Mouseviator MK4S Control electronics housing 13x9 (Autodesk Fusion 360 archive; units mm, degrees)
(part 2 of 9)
sketch "Sketch1" plane through (0, 0, 5) normal (0, 0, 1) x axis (-1, 0, 0)
  line L1 (-98.9644, -53.9879) -> (-98.9644, -59.9879)
  line L2 (-92.9644, -53.9879) -> (-98.9644, -53.9879)
  line L3 (-92.9644, -59.9879) -> (-92.9644, -53.9879)
  line L4 (-98.9644, -59.9879) -> (-92.9644, -59.9879)
  line L5 (-12.9644, 60.0121) -> (-12.9644, 66.0121)
  line L6 (-18.9644, 60.0121) -> (-12.9644, 60.0121)
  line L7 (-18.9644, 66.0121) -> (-18.9644, 60.0121)
  line L8 (-12.9644, 66.0121) -> (-18.9644, 66.0121)
  line L9 (-45.9644, -51.9879) -> (-20.9644, -51.9879)
  line L10 (-40.9644, -54.9879) -> (-45.9644, -51.9879)
  line L11 (-70.9644, -54.9879) -> (-40.9644, -54.9879)
  line L12 (-65.9644, -51.9879) -> (-70.9644, -54.9879)
  line L13 (-90.9644, -51.9879) -> (-65.9644, -51.9879)
  line L14 (-90.9644, -6.9879) -> (-90.9644, -51.9879)
  line L15 (-93.9644, -11.9879) -> (-90.9644, -6.9879)
  line L16 (-93.9644, 18.0121) -> (-93.9644, -11.9879)
  line L17 (-90.9644, 13.0121) -> (-93.9644, 18.0121)
  line L18 (-90.9644, 58.0121) -> (-90.9644, 13.0121)
  line L19 (-65.9644, 58.0121) -> (-90.9644, 58.0121)
  line L20 (-70.9644, 61.0121) -> (-65.9644, 58.0121)
  line L21 (-40.9644, 61.0121) -> (-70.9644, 61.0121)
  line L22 (-45.9644, 58.0121) -> (-40.9644, 61.0121)
  line L23 (-20.9644, 58.0121) -> (-45.9644, 58.0121)
  line L24 (-20.9644, 13.0121) -> (-20.9644, 58.0121)
  line L25 (-17.9644, 18.0121) -> (-20.9644, 13.0121)
  line L26 (-17.9644, -11.9879) -> (-17.9644, 18.0121)
  line L27 (-20.9644, -6.9879) -> (-17.9644, -11.9879)
  line L28 (-20.9644, -51.9879) -> (-20.9644, -6.9879)
  line L29 (-12.9644, -53.9879) -> (-18.9644, -53.9879)
  line L30 (-12.9644, -59.9879) -> (-12.9644, -53.9879)
  line L31 (-18.9644, -59.9879) -> (-12.9644, -59.9879)
  line L32 (-18.9644, -53.9879) -> (-18.9644, -59.9879)
  line L33 (-98.9644, 60.0121) -> (-92.9644, 60.0121)
  line L34 (-98.9644, 66.0121) -> (-98.9644, 60.0121)
  line L35 (-92.9644, 66.0121) -> (-98.9644, 66.0121)
  line L36 (-92.9644, 60.0121) -> (-92.9644, 66.0121)
  line L37 (-10.9644, -6.9879) -> (-10.9644, -61.9879)
  line L38 (-13.9644, -11.9879) -> (-10.9644, -6.9879)
  line L39 (-13.9644, 18.0121) -> (-13.9644, -11.9879)
  line L40 (-10.9644, 13.0121) -> (-13.9644, 18.0121)
  line L41 (-10.9644, 68.0121) -> (-10.9644, 13.0121)
  line L42 (-45.9644, 68.0121) -> (-10.9644, 68.0121)
  line L43 (-40.9644, 65.0121) -> (-45.9644, 68.0121)
  line L44 (-70.9644, 65.0121) -> (-40.9644, 65.0121)
  line L45 (-65.9644, 68.0121) -> (-70.9644, 65.0121)
  line L46 (-100.9644, 68.0121) -> (-65.9644, 68.0121)
  line L47 (-100.9644, 13.0121) -> (-100.9644, 68.0121)
  line L48 (-97.9644, 18.0121) -> (-100.9644, 13.0121)
  line L49 (-97.9644, -11.9879) -> (-97.9644, 18.0121)
  line L50 (-100.9644, -6.9879) -> (-97.9644, -11.9879)
  line L51 (-100.9644, -61.9879) -> (-100.9644, -6.9879)
  line L52 (-65.9644, -61.9879) -> (-100.9644, -61.9879)
  line L53 (-70.9644, -58.9879) -> (-65.9644, -61.9879)
  line L54 (-40.9644, -58.9879) -> (-70.9644, -58.9879)
  line L55 (-45.9644, -61.9879) -> (-40.9644, -58.9879)
  line L56 (-10.9644, -61.9879) -> (-45.9644, -61.9879)
  line L57 (-100.9644, -61.9879) -> (-10.9644, -61.9879)
  line L58 (-99.9644, -60.9879) -> (-100.9644, -61.9879)
  line L59 (-91.9644, -60.9879) -> (-99.9644, -60.9879)
  line L60 (-91.9644, -59.9879) -> (-91.9644, -60.9879)
  line L61 (-19.9644, -59.9879) -> (-91.9644, -59.9879)
  line L62 (-19.9644, -60.9879) -> (-19.9644, -59.9879)
  line L63 (-11.9644, -60.9879) -> (-19.9644, -60.9879)
  line L64 (-10.9644, -61.9879) -> (-11.9644, -60.9879)
  line L65 (-99.9437, -61.0379) -> (-100.8937, -61.9879)
  line L66 (-91.9144, -61.0379) -> (-99.9437, -61.0379)
  line L67 (-91.9144, -60.0379) -> (-91.9144, -61.0379)
  line L68 (-20.0144, -60.0379) -> (-91.9144, -60.0379)
  line L69 (-20.0144, -61.0379) -> (-20.0144, -60.0379)
  line L70 (-11.9851, -61.0379) -> (-20.0144, -61.0379)
  line L71 (-11.0351, -61.9879) -> (-11.9851, -61.0379)
  circle C1 centre (-24.4644, 61.5121) radius 1.7
  circle C2 centre (-93.9644, 54.5121) radius 1.7
  circle C3 centre (-87.4644, -55.4879) radius 1.7
  circle C4 centre (-17.4644, -48.4879) radius 1.7
  circle C5 centre (-24.4644, -55.4879) radius 1.7
  circle C6 centre (-93.9644, -48.4879) radius 1.7
  circle C7 centre (-87.4644, 61.5121) radius 1.7
  circle C8 centre (-17.4644, 54.5121) radius 1.7
  point P46 (-10.9644, -61.9879)
  point P74 (-10.9644, -61.9879)
  point P61 (-100.9644, -61.9879)
  point P76 (-100.9644, -61.9879)
  point P68 (-99.9644, -60.9879)
  point P77 (-99.9644, -60.9879)
  point P69 (-91.9644, -60.9879)
  point P78 (-91.9644, -60.9879)
  point P70 (-91.9644, -59.9879)
  point P79 (-91.9644, -59.9879)
  point P71 (-19.9644, -59.9879)
  point P80 (-19.9644, -59.9879)
  point P72 (-19.9644, -60.9879)
  point P81 (-19.9644, -60.9879)
  point P73 (-11.9644, -60.9879)
  point P82 (-11.9644, -60.9879)
  point P89 (-11.0351, -61.9879)
  point P90 (-100.8937, -61.9879)
  point P75 (-100.9644, -61.9879)
  coincident P46 P74
  coincident P61 P76
  coincident P68 P77
  coincident P69 P78
  coincident P70 P79
  coincident P71 P80
  coincident P72 P81
  coincident P73 P82
  coincident L56 P89
  coincident L52 P90
  dimension "column_lock_spacing" = 2
  dimension "d228" distance L57 L70 = 0.95 (= "side_wall_thick1")
  dimension "d229" distance L57 L68 = 1.95 (= "side_wall_thick2")
  dimension "d230" distance L57 L66 = 0.95 (= "side_wall_thick1")
  dimension "d231" distance P74 P75 = 90 (= "plate_height")
  dimension "d232" distance L64 L71 = 0.05 (= "wall_clearance")
  dimension "d233" distance L58 L65 = 0.05 (= "wall_clearance")
  dimension "d234" angle L57 L58 = 45 (= "wall_rorner_angle")
  dimension "d235" distance P74 L69 = 9.05 (= "side_wall_col_length")
  dimension "d244" distance P75 L67 = 9.05 (= "side_wall_col_length")
extrude "Extrude1" new body sketch "Sketch1" profile of L52 L53 L55 L56 blind 69.9 (= "column_height - ( 2 * wall_clearance )") from offset 0.05 (= "wall_clearance")
sketch "Sketch2" plane through (0, 61.9879, 0) normal (0, 1, 0) x axis (-1, 0, 0)
  line L1 (-11.0351, 74.95) -> (-100.8937, 74.95)
  line L2 (-100.8937, 74.95) -> (-100.8937, 5.05)
  line L3 (-11.0351, 74.95) -> (-11.0351, 5.05)
  line L4 (-11.0351, 5.05) -> (-100.8937, 5.05)
  line L5 (-11.0351, 74.95) -> (-11.0351, 5.05)
  line L6 (-100.8937, 74.95) -> (-11.0351, 74.95)
  line L7 (-100.8937, 5.05) -> (-100.8937, 74.95)
  line L8 (-90.8937, 64.95) -> (-21.0351, 64.95)
  line L9 (-90.8937, 15.05) -> (-90.8937, 64.95)
  line L10 (-21.0351, 15.05) -> (-90.8937, 15.05)
  line L11 (-21.0351, 64.95) -> (-21.0351, 15.05)
  circle C1 centre (-95.9644, 60) radius 1.7
  circle C2 centre (-95.9644, 20) radius 1.7
  circle C3 centre (-15.9644, 20) radius 1.7
  circle C4 centre (-15.9644, 60) radius 1.7
hole "Hole1" HoleDepth 4 HoleDiameter 3.4 TipAngle 118
mirror_component "MirrorComponent3"
derived_instance "DerivedInstance3"
extrude "Extrude7" add sketch "left side holes" profile of C1 L13 L14 L15 L16 along normal blind 1.45 (= "( top_cover_thickness / 2 ) - wall_clearance")
extrude "Extrude3" cut sketch "base" profile of L9 L10 L11 L12 L13 L14 L15 L16 L17 L18 L19 L20 L21 L22 L23 L24 along normal blind 1.5 (= "top_cover_thickness / 2")
extrude "Extrude2" add sketch "Sketch1" along normal blind 2.5 (= "plate_thick / 2")
extrude "Extrude4" cut sketch "Sketch1" profile of L13 L12 L15 L14 L16 L17 C2 C3 C4 C5 along normal blind 2.55 (= "( plate_thick / 2 ) + wall_clearance")
sketch "Sketch1" plane through (0, 0, 0) normal (0, 0, 1) x axis (1, 0, 0)
  line L1 (-15, -9) -> (-15, 21)
  line L2 (-7, 6) -> (-28, 6)
  line L3 (-18, 16) -> (-18, 6)
  line L4 (-18, -4) -> (-18, 6)
  line L5 (-15, 21) -> (-18, 16)
  line L6 (-15, -9) -> (-18, -4)
  line L7 (-21, -9) -> (-18, -4)
  line L8 (-18, -4) -> (-18, 6)
  line L9 (-18, 16) -> (-18, 6)
  line L10 (-21, 21) -> (-18, 16)
  line L11 (-21, -9) -> (-21, 21)
  line L12 (-15.05, 20.8195) -> (-18, 15.9028)
  line L13 (-15.05, -8.8195) -> (-15.05, 20.8195)
  line L14 (-15.05, -8.8195) -> (-18, -3.9028)
  line L15 (-20.95, -8.8195) -> (-18, -3.9028)
  line L16 (-20.95, -8.8195) -> (-20.95, 20.8195)
  line L17 (-20.95, 20.8195) -> (-18, 15.9028)
  line L18 (-16.5, -15) -> (-16.5, 22.7414)
  circle C1 centre (-16.5, 11) radius 0.75
  circle C2 centre (-16.5, 11) radius 0.675
  circle C3 centre (-16.5, 1) radius 0.675
  circle C4 centre (-19.5, 11) radius 0.675
  circle C5 centre (-19.5, 1) radius 0.675
  point P2 (-15, 21)
  point P13 (-21, 21)
  point P3 (-15, -9)
  point P10 (-21, -9)
  point P6 (-18, 6)
  point P11 (-18, 6)
  point P7 (-18, 16)
  point P12 (-18, 16)
  point P8 (-18, -4)
  point P9 (-18, -4)
  point P22 (-16.5, 11)
  vertical L1
  horizontal L2
  perpendicular L2 L3
  perpendicular L2 L4
  symmetric P2 L3 P13
  symmetric P3 L3 P10
  symmetric P6 L3 P11
  symmetric P7 L3 P12
  symmetric L3 P8 P9
  parallel L1 L18
  coincident L18 P22
  symmetric L2 C2 C3
  symmetric L4 C2 C4
  symmetric L4 C3 C5
  dimension "d49_1" distance P6 P7 = 10 (= "join_width1")
  dimension "d50_1" distance P6 P8 = 10 (= "join_width1")
  dimension "d51_1" distance P2 P3 = 30 (= "join_width2 * 2")
  dimension "d52_1" distance L1 L3 = 3 (= "join_depth")
  dimension "joiner_spacing_3" = -0.05
  dimension "d256_1" distance L9 L18 = 1.5 (= "join_depth / 2")
  dimension "d257_1" diameter C1 = 1.5 (= "join_key_d")
  dimension "d258_1" distance L2 P22 = 5 (= "join_key_distance")
extrude "Extrude1" new body sketch "Sketch1" profile of L13 L12 L15 L14 L16 L17 along normal blind 5 (= "plate_thick") named "d54_1"
extrude "Extrude4" cut sketch "Sketch1" profile of L13 L12 L15 L14 L16 L17 C2 C3 C4 C5 along normal blind 2.55 (= "( plate_thick / 2 ) + wall_clearance") named "d260_1"
sketch "Sketch1" plane through (0, 0, 0) normal (0, 0, 1) x axis (1, 0, 0)
  line L1 (-15, -9) -> (-15, 21)
  line L2 (-7, 6) -> (-28, 6)
  line L3 (-18, 16) -> (-18, 6)
  line L4 (-18, -4) -> (-18, 6)
  line L5 (-15, 21) -> (-18, 16)
  line L6 (-15, -9) -> (-18, -4)
  line L7 (-18, -4) -> (-18, 6)
  line L8 (-18, 16) -> (-18, 6)
  line L9 (-15.05, 20.8195) -> (-18, 15.9028)
  line L10 (-15.05, -8.8195) -> (-15.05, 20.8195)
  line L11 (-15.05, -8.8195) -> (-18, -3.9028)
  line L12 (-16.5, -15) -> (-16.5, 22.7414)
  circle C1 centre (-16.5, 11) radius 0.75
  circle C2 centre (-16.5, 11) radius 0.675
  circle C3 centre (-16.5, 1) radius 0.675
  point P6 (-18, 6)
  point P10 (-18, 6)
  point P7 (-18, 16)
  point P11 (-18, 16)
  point P8 (-18, -4)
  point P9 (-18, -4)
  point P17 (-16.5, 11)
  point P2 (-15, 21)
  point P3 (-15, -9)
  vertical L1
  horizontal L2
  perpendicular L2 L3
  perpendicular L2 L4
  symmetric P6 L3 P10
  symmetric P7 L3 P11
  symmetric L3 P8 P9
  parallel L1 L12
  coincident L12 P17
  symmetric L2 C2 C3
  dimension "d49_1_2" distance P6 P7 = 10 (= "join_width1")
  dimension "d50_1_2" distance P6 P8 = 10 (= "join_width1")
  dimension "d51_1_2" distance P2 P3 = 30 (= "join_width2 * 2")
  dimension "d52_1_2" distance L1 L3 = 3 (= "join_depth")
  dimension "joiner_spacing_3_2" = -0.05
  dimension "d256_1_2" distance L8 L12 = 1.5 (= "join_depth / 2")
  dimension "d257_1_2" diameter C1 = 1.5 (= "join_key_d")
  dimension "d258_1_2" distance L2 P17 = 5 (= "join_key_distance")
position "Position3"
extrude "Extrude5" new body sketch "Sketch1" profile of L3 L7 L10 L9 L11 C2 C3 along normal blind 5 (= "plate_thick")
extrude "Extrude6" cut sketch "Sketch1" profile of L3 L7 L10 L9 L11 C2 C3 along normal blind 2.55 (= "( plate_thick / 2 ) + wall_clearance")
extrude "Extrude4" cut sketch "base" profile of L1 L2 L3 L4 L25 L26 L27 L28 C1 C2 L29 L30 L31 L32 C3 C4 L33 L34 C5 L35 C6 L36 L37 L38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 blind -1.5 (= "-( top_cover_thickness / 2 )") from offset 3 (= "top_cover_thickness")
extrude "Extrude5" cut sketch "base" profile of C1 C2 C3 C4 C5 C6 C7 C8 no distance stored
sketch "Sketch1" plane through (0, 0, 0) normal (0, 0, 1) x axis (1, 0, 0)
  line L1 (-15, -9) -> (-15, 21)
  line L2 (-7, 6) -> (-28, 6)
  line L3 (-18, 16) -> (-18, 6)
  line L4 (-18, -4) -> (-18, 6)
  line L5 (-15, 21) -> (-18, 16)
  line L6 (-15, -9) -> (-18, -4)
  line L7 (-18, -4) -> (-18, 6)
  line L8 (-18, 16) -> (-18, 6)
  line L9 (-15.05, 20.8195) -> (-18, 15.9028)
  line L10 (-15.05, -8.8195) -> (-15.05, 20.8195)
  line L11 (-15.05, -8.8195) -> (-18, -3.9028)
  line L12 (-16.5, -15) -> (-16.5, 22.7414)
  circle C1 centre (-16.5, 11) radius 0.75
  circle C2 centre (-16.5, 11) radius 0.675
  circle C3 centre (-16.5, 1) radius 0.675
  point P6 (-18, 6)
  point P10 (-18, 6)
  point P7 (-18, 16)
  point P11 (-18, 16)
  point P8 (-18, -4)
  point P9 (-18, -4)
  point P17 (-16.5, 11)
  point P2 (-15, 21)
  point P3 (-15, -9)
  vertical L1
  horizontal L2
  perpendicular L2 L3
  perpendicular L2 L4
  symmetric P6 L3 P10
  symmetric P7 L3 P11
  symmetric L3 P8 P9
  parallel L1 L12
  coincident L12 P17
  symmetric L2 C2 C3
  dimension "d49_1_2_1" distance P6 P7 = 10 (= "join_width1")
  dimension "d50_1_2_1" distance P6 P8 = 10 (= "join_width1")
  dimension "d51_1_2_1" distance P2 P3 = 30 (= "join_width2 * 2")
  dimension "d52_1_2_1" distance L1 L3 = 3 (= "join_depth")
  dimension "joiner_spacing_3_2_1" = -0.05
  dimension "d256_1_2_1" distance L8 L12 = 1.5 (= "join_depth / 2")
  dimension "d257_1_2_1" diameter C1 = 1.5 (= "join_key_d")
  dimension "d258_1_2_1" distance L2 P17 = 5 (= "join_key_distance")
position "Position4"
extrude "Extrude5" new body sketch "Sketch1" profile of L3 L7 L10 L9 L11 C2 C3 along normal blind 3 (= "top_cover_thickness") named "d262_1"
extrude "Extrude6" cut sketch "Sketch1" profile of L3 L7 L10 L9 L11 C2 C3 along normal blind 1.55 (= "( top_cover_thickness / 2 ) + wall_clearance") named "d264_1"
sketch "Sketch1" plane through (0, 0, 0) normal (0, 0, 1) x axis (1, 0, 0)
  line L1 (-15, -9) -> (-15, 21)
  line L2 (-7, 6) -> (-28, 6)
  line L3 (-18, 16) -> (-18, 6)
  line L4 (-18, -4) -> (-18, 6)
  line L5 (-15, 21) -> (-18, 16)
  line L6 (-15, -9) -> (-18, -4)
  line L7 (-21, -9) -> (-18, -4)
  line L8 (-18, -4) -> (-18, 6)
  line L9 (-18, 16) -> (-18, 6)
  line L10 (-21, 21) -> (-18, 16)
  line L11 (-21, -9) -> (-21, 21)
  line L12 (-15.05, 20.8195) -> (-18, 15.9028)
  line L13 (-15.05, -8.8195) -> (-15.05, 20.8195)
  line L14 (-15.05, -8.8195) -> (-18, -3.9028)
  line L15 (-20.95, -8.8195) -> (-18, -3.9028)
  line L16 (-20.95, -8.8195) -> (-20.95, 20.8195)
  line L17 (-20.95, 20.8195) -> (-18, 15.9028)
  line L18 (-16.5, -15) -> (-16.5, 22.7414)
  circle C1 centre (-16.5, 11) radius 0.75
  circle C2 centre (-16.5, 11) radius 0.675
  circle C3 centre (-16.5, 1) radius 0.675
  circle C4 centre (-19.5, 11) radius 0.675
  circle C5 centre (-19.5, 1) radius 0.675
  point P2 (-15, 21)
  point P13 (-21, 21)
  point P3 (-15, -9)
  point P10 (-21, -9)
  point P6 (-18, 6)
  point P11 (-18, 6)
  point P7 (-18, 16)
  point P12 (-18, 16)
  point P8 (-18, -4)
  point P9 (-18, -4)
  point P22 (-16.5, 11)
  vertical L1
  horizontal L2
  perpendicular L2 L3
  perpendicular L2 L4
  symmetric P2 L3 P13
  symmetric P3 L3 P10
  symmetric P6 L3 P11
  symmetric P7 L3 P12
  symmetric L3 P8 P9
  parallel L1 L18
  coincident L18 P22
  symmetric L2 C2 C3
  symmetric L4 C2 C4
  symmetric L4 C3 C5
  dimension "d49_1_1" distance P6 P7 = 10 (= "join_width1")
  dimension "d50_1_1" distance P6 P8 = 10 (= "join_width1")
  dimension "d51_1_1" distance P2 P3 = 30 (= "join_width2 * 2")
  dimension "d52_1_1" distance L1 L3 = 3 (= "join_depth")
  dimension "joiner_spacing_3_3" = -0.05
  dimension "d256_1_1" distance L9 L18 = 1.5 (= "join_depth / 2")
  dimension "d257_1_1" diameter C1 = 1.5 (= "join_key_d")
  dimension "d258_1_1" distance L2 P22 = 5 (= "join_key_distance")
extrude "Extrude1" new body sketch "Sketch1" profile of L13 L12 L15 L14 L16 L17 C2 C3 C4 C5 along normal blind 3 (= "top_cover_thickness") named "d54_1_1"
extrude "Extrude4" cut sketch "Sketch1" profile of L13 L12 L15 L14 L16 L17 C2 C3 C4 C5 along normal blind 1.55 (= "( top_cover_thickness / 2 ) + wall_clearance") named "d260_1_1"
position "Position5"
sketch "base" plane through (0, 0, 0) normal (0, 0, 1) x axis (1, 0, 0)
  line L1 (12.9644, 53.9879) -> (18.9644, 53.9879)
  line L2 (12.9644, 59.9879) -> (12.9644, 53.9879)
  line L3 (18.9644, 59.9879) -> (12.9644, 59.9879)
  line L4 (18.9644, 53.9879) -> (18.9644, 59.9879)
  line L5 (13.0144, 54.0379) -> (18.9144, 54.0379)
  line L6 (13.0144, 59.9379) -> (13.0144, 54.0379)
  line L7 (18.9144, 59.9379) -> (13.0144, 59.9379)
  line L8 (18.9144, 54.0379) -> (18.9144, 59.9379)
  line L9 (11.9644, 52.9879) -> (19.9644, 52.9879)
  line L10 (11.9644, 60.9879) -> (11.9644, 52.9879)
  line L11 (19.9644, 60.9879) -> (11.9644, 60.9879)
  line L12 (19.9644, 52.9879) -> (19.9644, 60.9879)
  dimension "d67_1" = 0.05
  dimension "d68_1" = -1
extrude "Extrude2" new body sketch "base" profile of L1 L2 L3 L4 L9 L10 L11 L12 blind 70 (= "column_height") named "d73_1" from offset 5 (= "plate_thick") named "d72_1"
extrude "Extrude3" add sketch "Sketch1" profile of L36 L35 L38 L37 along normal blind 75 (= "plate_thick + column_height") named "d75_1"
sketch "supports bottom" plane through (0, 0, 5) normal (0, 0, 1) x axis (-1, 0, 0)
  line L1 (-98.9644, -53.9879) -> (-98.9644, -59.9879)
  line L2 (-92.9644, -53.9879) -> (-98.9644, -53.9879)
  line L3 (-92.9644, -59.9879) -> (-92.9644, -53.9879)
  line L4 (-98.9644, -59.9879) -> (-92.9644, -59.9879)
  line L5 (-12.9644, 60.0121) -> (-12.9644, 66.0121)
  line L6 (-18.9644, 60.0121) -> (-12.9644, 60.0121)
  line L7 (-18.9644, 66.0121) -> (-18.9644, 60.0121)
  line L8 (-12.9644, 66.0121) -> (-18.9644, 66.0121)
  line L9 (-45.9644, -51.9879) -> (-20.9644, -51.9879)
  line L10 (-40.9644, -54.9879) -> (-45.9644, -51.9879)
  line L11 (-70.9644, -54.9879) -> (-40.9644, -54.9879)
  line L12 (-65.9644, -51.9879) -> (-70.9644, -54.9879)
  line L13 (-90.9644, -51.9879) -> (-65.9644, -51.9879)
  line L14 (-90.9644, -6.9879) -> (-90.9644, -51.9879)
  line L15 (-93.9644, -11.9879) -> (-90.9644, -6.9879)
  line L16 (-93.9644, 18.0121) -> (-93.9644, -11.9879)
  line L17 (-90.9644, 13.0121) -> (-93.9644, 18.0121)
  line L18 (-90.9644, 58.0121) -> (-90.9644, 13.0121)
  line L19 (-65.9644, 58.0121) -> (-90.9644, 58.0121)
  line L20 (-70.9644, 61.0121) -> (-65.9644, 58.0121)
  line L21 (-40.9644, 61.0121) -> (-70.9644, 61.0121)
  line L22 (-45.9644, 58.0121) -> (-40.9644, 61.0121)
  line L23 (-20.9644, 58.0121) -> (-45.9644, 58.0121)
  line L24 (-20.9644, 13.0121) -> (-20.9644, 58.0121)
  line L25 (-17.9644, 18.0121) -> (-20.9644, 13.0121)
  line L26 (-17.9644, -11.9879) -> (-17.9644, 18.0121)
  line L27 (-20.9644, -6.9879) -> (-17.9644, -11.9879)
  line L28 (-20.9644, -51.9879) -> (-20.9644, -6.9879)
  line L29 (-12.9644, -53.9879) -> (-18.9644, -53.9879)
  line L30 (-12.9644, -59.9879) -> (-12.9644, -53.9879)
  line L31 (-18.9644, -59.9879) -> (-12.9644, -59.9879)
  line L32 (-18.9644, -53.9879) -> (-18.9644, -59.9879)
  line L33 (-98.9644, 60.0121) -> (-92.9644, 60.0121)
  line L34 (-98.9644, 66.0121) -> (-98.9644, 60.0121)
  line L35 (-92.9644, 66.0121) -> (-98.9644, 66.0121)
  line L36 (-92.9644, 60.0121) -> (-92.9644, 66.0121)
  line L37 (-10.9644, -6.9879) -> (-10.9644, -61.9879)
  line L38 (-13.9644, -11.9879) -> (-10.9644, -6.9879)
  line L39 (-13.9644, 18.0121) -> (-13.9644, -11.9879)
  line L40 (-10.9644, 13.0121) -> (-13.9644, 18.0121)
  line L41 (-10.9644, 68.0121) -> (-10.9644, 13.0121)
  line L42 (-45.9644, 68.0121) -> (-10.9644, 68.0121)
  line L43 (-40.9644, 65.0121) -> (-45.9644, 68.0121)
  line L44 (-70.9644, 65.0121) -> (-40.9644, 65.0121)
  line L45 (-65.9644, 68.0121) -> (-70.9644, 65.0121)
  line L46 (-100.9644, 68.0121) -> (-65.9644, 68.0121)
  line L47 (-100.9644, 13.0121) -> (-100.9644, 68.0121)
  line L48 (-97.9644, 18.0121) -> (-100.9644, 13.0121)
  line L49 (-97.9644, -11.9879) -> (-97.9644, 18.0121)
  line L50 (-100.9644, -6.9879) -> (-97.9644, -11.9879)
  line L51 (-100.9644, -61.9879) -> (-100.9644, -6.9879)
  line L52 (-65.9644, -61.9879) -> (-100.9644, -61.9879)
  line L53 (-70.9644, -58.9879) -> (-65.9644, -61.9879)
  line L54 (-40.9644, -58.9879) -> (-70.9644, -58.9879)
  line L55 (-45.9644, -61.9879) -> (-40.9644, -58.9879)
  line L56 (-10.9644, -61.9879) -> (-45.9644, -61.9879)
  line L57 (-11.9644, -52.9879) -> (-19.9644, -52.9879)
  line L58 (-11.9644, -60.9879) -> (-11.9644, -52.9879)
  line L59 (-19.9644, -60.9879) -> (-11.9644, -60.9879)
  line L60 (-19.9644, -52.9879) -> (-19.9644, -60.9879)
  line L61 (-14.9644, -52.9879) -> (-12.9644, -52.9879)
  line L62 (-14.9644, -42.9879) -> (-14.9644, -52.9879)
  line L63 (-12.9644, -42.9879) -> (-14.9644, -42.9879)
  line L64 (-12.9644, -52.9879) -> (-12.9644, -42.9879)
  line L65 (-29.9644, -59.9879) -> (-19.9644, -59.9879)
  line L66 (-29.9644, -57.9879) -> (-29.9644, -59.9879)
  line L67 (-19.9644, -57.9879) -> (-29.9644, -57.9879)
  line L68 (-19.9644, -59.9879) -> (-19.9644, -57.9879)
  circle C1 centre (-24.4644, 61.5121) radius 1.7
  circle C2 centre (-93.9644, 54.5121) radius 1.7
  circle C3 centre (-87.4644, -55.4879) radius 1.7
  circle C4 centre (-17.4644, -48.4879) radius 1.7
  circle C5 centre (-24.4644, -55.4879) radius 1.7
  circle C6 centre (-93.9644, -48.4879) radius 1.7
  circle C7 centre (-87.4644, 61.5121) radius 1.7
  circle C8 centre (-17.4644, 54.5121) radius 1.7
  circle C9 centre (-17.4644, -48.4879) radius 1.7
  circle C10 centre (-24.4644, -55.4879) radius 1.7
  circle C11 centre (-17.4644, -48.4879) radius 3.15
  circle C12 centre (-24.4644, -55.4879) radius 3.15
  point P70 (-12.9644, -52.9879)
  point P74 (-19.9644, -59.9879)
  point P71 (-14.9644, -52.9879)
  point P73 (-12.9644, -42.9879)
  point P75 (-29.9644, -59.9879)
  point P77 (-19.9644, -57.9879)
  horizontal L61
  vertical L62
  horizontal L63
  vertical L64
  coincident L57 P70
  horizontal L65
  vertical L66
  horizontal L67
  vertical L68
  coincident L60 P74
  concentric C9 C11
  concentric C10 C12
  dimension "column_support_width_1" distance P70 P71 = 2
  dimension "column_support_height_1" distance P70 P73 = 10
  dimension "d79_1" distance P74 P75 = 10 (= "column_support_height_1")
  dimension "d80_1" distance P74 P77 = 2 (= "column_support_width_1")
  dimension "M3_head_d_1" diameter C11 = 6.3
  dimension "d85_1" diameter C12 = 6.3 (= "M3_head_d_1")
extrude "Extrude5" add sketch "supports bottom" profile of L53 L57 L60 L61 L62 L63 L64 L65 L66 L67 L68 C11 C12 along normal blind 10 (= "column_support_height_1") named "d86_1"
chamfer "Chamfer2" distance 10 (= "column_support_height_1") named "d88_1"
sketch "left side holes" plane through (0, 0, 75) normal (0, 0, 1) x axis (-1, 0, 0)
  line L1 (-11.9644, -60.9879) -> (-19.9644, -60.9879)
  line L2 (-11.9644, -52.9879) -> (-11.9644, -60.9879)
  line L3 (-19.9644, -52.9879) -> (-11.9644, -52.9879)
  line L4 (-19.9644, -60.9879) -> (-19.9644, -52.9879)
  line L5 (-19.9644, -57.9879) -> (-29.9644, -57.9879)
  line L6 (-19.9644, -59.9879) -> (-19.9644, -57.9879)
  line L7 (-29.9644, -59.9879) -> (-19.9644, -59.9879)
  line L8 (-29.9644, -57.9879) -> (-29.9644, -59.9879)
  line L9 (-14.9644, -42.9879) -> (-14.9644, -52.9879)
  line L10 (-12.9644, -42.9879) -> (-14.9644, -42.9879)
  line L11 (-14.9644, -52.9879) -> (-12.9644, -52.9879)
  line L12 (-12.9644, -52.9879) -> (-12.9644, -42.9879)
  line L13 (-18.9144, -59.9379) -> (-13.0144, -59.9379)
  line L14 (-18.9144, -54.0379) -> (-18.9144, -59.9379)
  line L15 (-13.0144, -54.0379) -> (-18.9144, -54.0379)
  line L16 (-13.0144, -59.9379) -> (-13.0144, -54.0379)
  line L17 (-18.9644, -59.9879) -> (-12.9644, -59.9879)
  line L18 (-18.9644, -53.9879) -> (-18.9644, -59.9879)
  line L19 (-12.9644, -53.9879) -> (-18.9644, -53.9879)
  line L20 (-12.9644, -59.9879) -> (-12.9644, -53.9879)
  circle C1 centre (-15.9644, -56.9879) radius 1.7
  dimension "M3_d_1" diameter C1 = 3.4
extrude "Extrude6" add sketch "left side holes" profile of L3 L4 L5 L6 L7 L8 L9 L10 L11 L12 against normal blind 10 named "d90_1" (magnitude of "-column_support_height_1")
chamfer "Chamfer3" distance 10 (= "column_support_height_1") named "d92_1"
hole "Hole1" HoleDepth 10 (= "column_support_height_1") named "d93_1" HoleDiameter 3.4 named "d94_1" TipAngle 118 named "d95_1"
sketch "Sketch4" plane through (0, 60.9879, 0) normal (0, 1, 0) x axis (-1, 0, 0)
  line L1 (-11.9644, 5) -> (-19.9644, 5)
  line L2 (-11.9644, 75) -> (-11.9644, 5)
  line L3 (-19.9644, 75) -> (-11.9644, 75)
  line L4 (-19.9644, 5) -> (-19.9644, 75)
  line L5 (-23.511, 60) -> (-11.9644, 60)
  line L6 (-25, 20) -> (-11.9644, 20)
  circle C1 centre (-15.9644, 60) radius 1.7
  circle C2 centre (-15.9644, 20) radius 1.7
  point P7 (-11.9644, 60)
  point P8 (-11.9644, 60)
  point P6 (-11.9644, 20)
  point P10 (-11.9644, 20)
  point P12 (-15.9644, 60)
  point P13 (-15.9644, 20)
  coincident P7 P8
  perpendicular L4 L5
  coincident P6 P10
  perpendicular L2 L6
  coincident L5 P12
  coincident L6 P13
  dimension "d103_1" diameter C1 = 3.4 (= "M3_d_1")
  dimension "d104_1" diameter C2 = 3.4 (= "M3_d_1")
  dimension "d105_1" distance L2 P12 = 4 (= "support_column_side / 2")
  dimension "d106_1" distance L2 P13 = 4 (= "support_column_side / 2")
hole "Hole3" HoleDepth 5.76 (= "support_column_side * 0.72") named "d110_1" HoleDiameter 3.4 named "d111_1" TipAngle 180 named "d112_1"
extrude "Extrude7" add sketch "left side holes" profile of C1 L13 L14 L15 L16 along normal blind 1.45 (= "( top_cover_thickness / 2 ) - wall_clearance") named "d236_1"
position "Position6"
work_plane "WorkPlane3" AlongDistance 1 (= "plate_square_thick - side_wall_col_length + wall_clearance")
sketch "Sketch5" plane through (11.9644, 0, 0) normal (-1, 0, 0) x axis (0, -1, 0)
  line L1 (-52.9879, 5) -> (-60.9879, 5)
  line L2 (-52.9879, 75) -> (-52.9879, 5)
  line L3 (-60.9879, 75) -> (-52.9879, 75)
  line L4 (-60.9879, 5) -> (-60.9879, 75)
  line L5 (-56.5129, 75) -> (-60.9879, 75)
  line L6 (-56.5129, 65) -> (-56.5129, 75)
  line L7 (-60.9879, 65) -> (-56.5129, 65)
  line L8 (-60.9879, 75) -> (-60.9879, 65)
  line L9 (-56.4129, 5) -> (-60.9879, 5)
  line L10 (-56.4129, 15) -> (-56.4129, 5)
  line L11 (-60.9879, 15) -> (-56.4129, 15)
  line L12 (-60.9879, 5) -> (-60.9879, 15)
  point P5 (-60.9879, 75)
  point P6 (-60.9879, 75)
  point P2 (-60.9879, 5)
  point P10 (-60.9879, 5)
  point P7 (-56.5129, 75)
  point P11 (-56.4129, 5)
  point P13 (-60.9879, 15)
  horizontal L5
  vertical L6
  horizontal L7
  vertical L8
  coincident P5 P6
  horizontal L9
  vertical L10
  horizontal L11
  vertical L12
  coincident P2 P10
  dimension "d271" distance P6 P7 = 4.475 (= "side_wall_col_length / 2 - wall_clearance")
  dimension "d272" distance L5 L7 = 10 (= "column_support_height")
  dimension "d273" distance P10 P11 = 4.575 (= "side_wall_col_length / 2 + wall_clearance")
  dimension "d274" distance P10 P13 = 10 (= "column_support_height")
extrude "Extrude8" add sketch "Sketch5" profile of L1 L3 L4 L5 L6 L7 L8 L9 L10 L11 L12 along normal blind 2 (= "2 * ( plate_square_thick - side_wall_col_length + wall_clearance )")
mirror "Mirror1" mirrorStitchTolerance 0.1
sketch "Sketch1" plane through (0, 0, 5) normal (0, 0, 1) x axis (-1, 0, 0)
  line L1 (-98.9644, -53.9879) -> (-98.9644, -59.9879)
  line L2 (-92.9644, -53.9879) -> (-98.9644, -53.9879)
  line L3 (-92.9644, -59.9879) -> (-92.9644, -53.9879)
  line L4 (-98.9644, -59.9879) -> (-92.9644, -59.9879)
  line L5 (-98.9644, 60.0121) -> (-92.9644, 60.0121)
  line L6 (-98.9644, 66.0121) -> (-98.9644, 60.0121)
  line L7 (-92.9644, 66.0121) -> (-98.9644, 66.0121)
  line L8 (-92.9644, 60.0121) -> (-92.9644, 66.0121)
  line L9 (-12.9644, 60.0121) -> (-12.9644, 66.0121)
  line L10 (-18.9644, 60.0121) -> (-12.9644, 60.0121)
  line L11 (-18.9644, 66.0121) -> (-18.9644, 60.0121)
  line L12 (-12.9644, 66.0121) -> (-18.9644, 66.0121)
  line L13 (-12.9644, -53.9879) -> (-18.9644, -53.9879)
  line L14 (-12.9644, -59.9879) -> (-12.9644, -53.9879)
  line L15 (-18.9644, -59.9879) -> (-12.9644, -59.9879)
  line L16 (-18.9644, -53.9879) -> (-18.9644, -59.9879)
  line L17 (-45.9644, -51.9879) -> (-20.9644, -51.9879)
  line L18 (-40.9644, -54.9879) -> (-45.9644, -51.9879)
  line L19 (-70.9644, -54.9879) -> (-40.9644, -54.9879)
  line L20 (-65.9644, -51.9879) -> (-70.9644, -54.9879)
  line L21 (-90.9644, -51.9879) -> (-65.9644, -51.9879)
  line L22 (-90.9644, -6.9879) -> (-90.9644, -51.9879)
  line L23 (-93.9644, -11.9879) -> (-90.9644, -6.9879)
  line L24 (-93.9644, 18.0121) -> (-93.9644, -11.9879)
  line L25 (-90.9644, 13.0121) -> (-93.9644, 18.0121)
  line L26 (-90.9644, 58.0121) -> (-90.9644, 13.0121)
  line L27 (-65.9644, 58.0121) -> (-90.9644, 58.0121)
  line L28 (-70.9644, 61.0121) -> (-65.9644, 58.0121)
  line L29 (-40.9644, 61.0121) -> (-70.9644, 61.0121)
  line L30 (-45.9644, 58.0121) -> (-40.9644, 61.0121)
  line L31 (-20.9644, 58.0121) -> (-45.9644, 58.0121)
  line L32 (-20.9644, 13.0121) -> (-20.9644, 58.0121)
  line L33 (-17.9644, 18.0121) -> (-20.9644, 13.0121)
  line L34 (-17.9644, -11.9879) -> (-17.9644, 18.0121)
  line L35 (-20.9644, -6.9879) -> (-17.9644, -11.9879)
  line L36 (-20.9644, -51.9879) -> (-20.9644, -6.9879)
  line L37 (-10.9644, -6.9879) -> (-10.9644, -61.9879)
  line L38 (-13.9644, -11.9879) -> (-10.9644, -6.9879)
  line L39 (-13.9644, 18.0121) -> (-13.9644, -11.9879)
  line L40 (-10.9644, 13.0121) -> (-13.9644, 18.0121)
  line L41 (-10.9644, 68.0121) -> (-10.9644, 13.0121)
  line L42 (-45.9644, 68.0121) -> (-10.9644, 68.0121)
  line L43 (-40.9644, 65.0121) -> (-45.9644, 68.0121)
  line L44 (-70.9644, 65.0121) -> (-40.9644, 65.0121)
  line L45 (-65.9644, 68.0121) -> (-70.9644, 65.0121)
  line L46 (-100.9644, 68.0121) -> (-65.9644, 68.0121)
  line L47 (-100.9644, 13.0121) -> (-100.9644, 68.0121)
  line L48 (-97.9644, 18.0121) -> (-100.9644, 13.0121)
  line L49 (-97.9644, -11.9879) -> (-97.9644, 18.0121)
  line L50 (-100.9644, -6.9879) -> (-97.9644, -11.9879)
  line L51 (-100.9644, -61.9879) -> (-100.9644, -6.9879)
  line L52 (-65.9644, -61.9879) -> (-100.9644, -61.9879)
  line L53 (-70.9644, -58.9879) -> (-65.9644, -61.9879)
  line L54 (-40.9644, -58.9879) -> (-70.9644, -58.9879)
  line L55 (-45.9644, -61.9879) -> (-40.9644, -58.9879)
  line L56 (-10.9644, -61.9879) -> (-45.9644, -61.9879)
  line L57 (-45.9644, -51.9879) -> (-20.9644, -51.9879)
  line L58 (-40.9644, -54.9879) -> (-55.9644, -54.9879)
  line L59 (-40.9644, -54.9879) -> (-45.9644, -51.9879)
  line L60 (-65.9644, -51.9879) -> (-70.9644, -54.9879)
  line L61 (-70.9644, -54.9879) -> (-55.9644, -54.9879)
  line L62 (-65.9644, -51.9879) -> (-90.9644, -51.9879)
  line L63 (-90.9644, -6.9879) -> (-90.9644, -51.9879)
  line L64 (-93.9644, -11.9879) -> (-93.9644, 3.0121)
  line L65 (-93.9644, -11.9879) -> (-90.9644, -6.9879)
  line L66 (-93.9644, 18.0121) -> (-90.9644, 13.0121)
  line L67 (-93.9644, 18.0121) -> (-93.9644, 3.0121)
  line L68 (-90.9644, 58.0121) -> (-90.9644, 13.0121)
  line L69 (-65.9644, 58.0121) -> (-90.9644, 58.0121)
  line L70 (-40.9644, 61.0121) -> (-45.9644, 58.0121)
  line L71 (-40.9644, 61.0121) -> (-55.9644, 61.0121)
  line L72 (-70.9644, 61.0121) -> (-55.9644, 61.0121)
  line L73 (-65.9644, 58.0121) -> (-70.9644, 61.0121)
  line L74 (-45.9644, 58.0121) -> (-20.9644, 58.0121)
  line L75 (-20.9644, 13.0121) -> (-20.9644, 58.0121)
  line L76 (-17.9644, 18.0121) -> (-17.9644, 3.0121)
  line L77 (-17.9644, -11.9879) -> (-17.9644, 3.0121)
  line L78 (-17.9644, -11.9879) -> (-20.9644, -6.9879)
  line L79 (-17.9644, 18.0121) -> (-20.9644, 13.0121)
  line L80 (-20.9644, -6.9879) -> (-20.9644, -51.9879)
  line L81 (-65.7839, -51.9379) -> (-70.7839, -54.9379)
  line L82 (-90.9144, -51.9379) -> (-65.7839, -51.9379)
  line L83 (-90.9144, -6.8074) -> (-90.9144, -51.9379)
  line L84 (-93.9144, -11.8074) -> (-90.9144, -6.8074)
  line L85 (-93.9144, 17.8316) -> (-93.9144, -11.8074)
  line L86 (-90.9144, 12.8316) -> (-93.9144, 17.8316)
  line L87 (-90.9144, 57.9621) -> (-90.9144, 12.8316)
  line L88 (-65.7839, 57.9621) -> (-90.9144, 57.9621)
  line L89 (-70.7839, 60.9621) -> (-65.7839, 57.9621)
  line L90 (-41.1449, 60.9621) -> (-70.7839, 60.9621)
  line L91 (-46.1449, 57.9621) -> (-41.1449, 60.9621)
  line L92 (-21.0144, 57.9621) -> (-46.1449, 57.9621)
  line L93 (-21.0144, 12.8316) -> (-21.0144, 57.9621)
  line L94 (-18.0144, 17.8316) -> (-21.0144, 12.8316)
  line L95 (-18.0144, -11.8074) -> (-18.0144, 17.8316)
  line L96 (-21.0144, -6.8074) -> (-18.0144, -11.8074)
  line L97 (-21.0144, -51.9379) -> (-21.0144, -6.8074)
  line L98 (-46.1449, -51.9379) -> (-21.0144, -51.9379)
  line L99 (-41.1449, -54.9379) -> (-46.1449, -51.9379)
  line L100 (-70.7839, -54.9379) -> (-41.1449, -54.9379)
  line L101 (-90.9144, 12.8316) -> (-90.9144, -6.8074)
  line L102 (-46.1449, -51.9379) -> (-65.7839, -51.9379)
  line L103 (-21.0144, 12.8316) -> (-21.0144, -6.8074)
  line L104 (-65.7839, 57.9621) -> (-46.1449, 57.9621)
  line L105 (-80.9144, -41.9379) -> (-31.0144, -41.9379)
  line L106 (-80.9144, 47.9621) -> (-80.9144, -41.9379)
  line L107 (-31.0144, 47.9621) -> (-80.9144, 47.9621)
  line L108 (-31.0144, -41.9379) -> (-31.0144, 47.9621)
  circle C1 centre (-24.4644, 61.5121) radius 1.7
  circle C2 centre (-93.9644, 54.5121) radius 1.7
  circle C3 centre (-87.4644, -55.4879) radius 1.7
  circle C4 centre (-17.4644, -48.4879) radius 1.7
  circle C5 centre (-24.4644, -55.4879) radius 1.7
  circle C6 centre (-93.9644, -48.4879) radius 1.7
  circle C7 centre (-87.4644, 61.5121) radius 1.7
  circle C8 centre (-17.4644, 54.5121) radius 1.7
  circle C9 centre (-60.9644, -53.4879) radius 0.75
  circle C10 centre (-50.9644, -53.4879) radius 0.75
  circle C11 centre (-92.4644, -1.9879) radius 0.75
  circle C12 centre (-92.4644, 8.0121) radius 0.75
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  horizontal L105
  vertical L106
  horizontal L107
  vertical L108
  dimension "d279" = 0.05 (= "wall_clearance")
  dimension "d289" distance L82 L105 = 10 (= "plate_square_thick")
  dimension "d290" distance L83 L106 = 10 (= "plate_square_thick")
  dimension "d291" distance L97 L108 = 10 (= "plate_square_thick")
  dimension "d292" distance L88 L107 = 10 (= "plate_square_thick")
extrude "Extrude1" new body sketch "Sketch1" along normal blind 5 (= "plate_thick")
extrude "Extrude2" add sketch "Sketch1" blind -2.45 (= "-( plate_thick / 2 ) + wall_clearance") from offset 5 (= "plate_thick")
sketch "base" plane through (0, 0, 0) normal (0, 0, 1) x axis (1, 0, 0)
  line L1 (12.9644, 53.9879) -> (18.9644, 53.9879)
  line L2 (12.9644, 59.9879) -> (12.9644, 53.9879)
  line L3 (18.9644, 59.9879) -> (12.9644, 59.9879)
  line L4 (18.9644, 53.9879) -> (18.9644, 59.9879)
  line L5 (13.0144, 54.0379) -> (18.9144, 54.0379)
  line L6 (13.0144, 59.9379) -> (13.0144, 54.0379)
  line L7 (18.9144, 59.9379) -> (13.0144, 59.9379)
  line L8 (18.9144, 54.0379) -> (18.9144, 59.9379)
  line L9 (11.9644, 52.9879) -> (19.9644, 52.9879)
  line L10 (11.9644, 60.9879) -> (11.9644, 52.9879)
  line L11 (19.9644, 60.9879) -> (11.9644, 60.9879)
  line L12 (19.9644, 52.9879) -> (19.9644, 60.9879)
  dimension "d67_1_1" = 0.05
  dimension "d68_1_1" = -1
extrude "Extrude2" new body sketch "base" profile of L1 L2 L3 L4 L9 L10 L11 L12 blind 70 (= "column_height") named "d73_1_1" from offset 5 (= "plate_thick") named "d72_1_1"
extrude "Extrude3" add sketch "Sketch1" profile of L36 L35 L38 L37 along normal blind 75 (= "plate_thick + column_height") named "d75_1_1"
sketch "supports bottom" plane through (0, 0, 5) normal (0, 0, 1) x axis (-1, 0, 0)
  line L1 (-98.9644, -53.9879) -> (-98.9644, -59.9879)
  line L2 (-92.9644, -53.9879) -> (-98.9644, -53.9879)
  line L3 (-92.9644, -59.9879) -> (-92.9644, -53.9879)
  line L4 (-98.9644, -59.9879) -> (-92.9644, -59.9879)
  line L5 (-12.9644, 60.0121) -> (-12.9644, 66.0121)
  line L6 (-18.9644, 60.0121) -> (-12.9644, 60.0121)
  line L7 (-18.9644, 66.0121) -> (-18.9644, 60.0121)
  line L8 (-12.9644, 66.0121) -> (-18.9644, 66.0121)
  line L9 (-45.9644, -51.9879) -> (-20.9644, -51.9879)
  line L10 (-40.9644, -54.9879) -> (-45.9644, -51.9879)
  line L11 (-70.9644, -54.9879) -> (-40.9644, -54.9879)
  line L12 (-65.9644, -51.9879) -> (-70.9644, -54.9879)
  line L13 (-90.9644, -51.9879) -> (-65.9644, -51.9879)
  line L14 (-90.9644, -6.9879) -> (-90.9644, -51.9879)
  line L15 (-93.9644, -11.9879) -> (-90.9644, -6.9879)
  line L16 (-93.9644, 18.0121) -> (-93.9644, -11.9879)
  line L17 (-90.9644, 13.0121) -> (-93.9644, 18.0121)
  line L18 (-90.9644, 58.0121) -> (-90.9644, 13.0121)
  line L19 (-65.9644, 58.0121) -> (-90.9644, 58.0121)
  line L20 (-70.9644, 61.0121) -> (-65.9644, 58.0121)
  line L21 (-40.9644, 61.0121) -> (-70.9644, 61.0121)
  line L22 (-45.9644, 58.0121) -> (-40.9644, 61.0121)
  line L23 (-20.9644, 58.0121) -> (-45.9644, 58.0121)
  line L24 (-20.9644, 13.0121) -> (-20.9644, 58.0121)
  line L25 (-17.9644, 18.0121) -> (-20.9644, 13.0121)
  line L26 (-17.9644, -11.9879) -> (-17.9644, 18.0121)
  line L27 (-20.9644, -6.9879) -> (-17.9644, -11.9879)
  line L28 (-20.9644, -51.9879) -> (-20.9644, -6.9879)
  line L29 (-12.9644, -53.9879) -> (-18.9644, -53.9879)
  line L30 (-12.9644, -59.9879) -> (-12.9644, -53.9879)
  line L31 (-18.9644, -59.9879) -> (-12.9644, -59.9879)
  line L32 (-18.9644, -53.9879) -> (-18.9644, -59.9879)
  line L33 (-98.9644, 60.0121) -> (-92.9644, 60.0121)
  line L34 (-98.9644, 66.0121) -> (-98.9644, 60.0121)
  line L35 (-92.9644, 66.0121) -> (-98.9644, 66.0121)
  line L36 (-92.9644, 60.0121) -> (-92.9644, 66.0121)
  line L37 (-10.9644, -6.9879) -> (-10.9644, -61.9879)
  line L38 (-13.9644, -11.9879) -> (-10.9644, -6.9879)
  line L39 (-13.9644, 18.0121) -> (-13.9644, -11.9879)
  line L40 (-10.9644, 13.0121) -> (-13.9644, 18.0121)
  line L41 (-10.9644, 68.0121) -> (-10.9644, 13.0121)
  line L42 (-45.9644, 68.0121) -> (-10.9644, 68.0121)
  line L43 (-40.9644, 65.0121) -> (-45.9644, 68.0121)
  line L44 (-70.9644, 65.0121) -> (-40.9644, 65.0121)
  line L45 (-65.9644, 68.0121) -> (-70.9644, 65.0121)
  line L46 (-100.9644, 68.0121) -> (-65.9644, 68.0121)
  line L47 (-100.9644, 13.0121) -> (-100.9644, 68.0121)
  line L48 (-97.9644, 18.0121) -> (-100.9644, 13.0121)
  line L49 (-97.9644, -11.9879) -> (-97.9644, 18.0121)
  line L50 (-100.9644, -6.9879) -> (-97.9644, -11.9879)
  line L51 (-100.9644, -61.9879) -> (-100.9644, -6.9879)
  line L52 (-65.9644, -61.9879) -> (-100.9644, -61.9879)
  line L53 (-70.9644, -58.9879) -> (-65.9644, -61.9879)
  line L54 (-40.9644, -58.9879) -> (-70.9644, -58.9879)
  line L55 (-45.9644, -61.9879) -> (-40.9644, -58.9879)
  line L56 (-10.9644, -61.9879) -> (-45.9644, -61.9879)
  line L57 (-11.9644, -52.9879) -> (-19.9644, -52.9879)
  line L58 (-11.9644, -60.9879) -> (-11.9644, -52.9879)
  line L59 (-19.9644, -60.9879) -> (-11.9644, -60.9879)
  line L60 (-19.9644, -52.9879) -> (-19.9644, -60.9879)
  line L61 (-14.9644, -52.9879) -> (-12.9644, -52.9879)
  line L62 (-14.9644, -42.9879) -> (-14.9644, -52.9879)
  line L63 (-12.9644, -42.9879) -> (-14.9644, -42.9879)
  line L64 (-12.9644, -52.9879) -> (-12.9644, -42.9879)
  line L65 (-29.9644, -59.9879) -> (-19.9644, -59.9879)
  line L66 (-29.9644, -57.9879) -> (-29.9644, -59.9879)
  line L67 (-19.9644, -57.9879) -> (-29.9644, -57.9879)
  line L68 (-19.9644, -59.9879) -> (-19.9644, -57.9879)
  circle C1 centre (-24.4644, 61.5121) radius 1.7
  circle C2 centre (-93.9644, 54.5121) radius 1.7
  circle C3 centre (-87.4644, -55.4879) radius 1.7
  circle C4 centre (-17.4644, -48.4879) radius 1.7
  circle C5 centre (-24.4644, -55.4879) radius 1.7
  circle C6 centre (-93.9644, -48.4879) radius 1.7
  circle C7 centre (-87.4644, 61.5121) radius 1.7
  circle C8 centre (-17.4644, 54.5121) radius 1.7
  circle C9 centre (-17.4644, -48.4879) radius 1.7
  circle C10 centre (-24.4644, -55.4879) radius 1.7
  circle C11 centre (-17.4644, -48.4879) radius 3.15
  circle C12 centre (-24.4644, -55.4879) radius 3.15
  point P70 (-12.9644, -52.9879)
  point P74 (-19.9644, -59.9879)
  point P71 (-14.9644, -52.9879)
  point P73 (-12.9644, -42.9879)
  point P75 (-29.9644, -59.9879)
  point P77 (-19.9644, -57.9879)
  horizontal L61
  vertical L62
  horizontal L63
  vertical L64
  coincident L57 P70
  horizontal L65
  vertical L66
  horizontal L67
  vertical L68
  coincident L60 P74
  concentric C9 C11
  concentric C10 C12
  dimension "column_support_width_1_1" distance P70 P71 = 2
  dimension "column_support_height_1_1" distance P70 P73 = 10
  dimension "d79_1_1" distance P74 P75 = 10 (= "column_support_height_1_1")
  dimension "d80_1_1" distance P74 P77 = 2 (= "column_support_width_1_1")
  dimension "M3_head_d_1_1" diameter C11 = 6.3
  dimension "d85_1_1" diameter C12 = 6.3 (= "M3_head_d_1_1")
extrude "Extrude5" add sketch "supports bottom" profile of L53 L57 L60 L61 L62 L63 L64 L65 L66 L67 L68 C11 C12 along normal blind 10 (= "column_support_height_1_1") named "d86_1_1"
chamfer "Chamfer2" distance 10 (= "column_support_height_1_1") named "d88_1_1"
sketch "left side holes" plane through (0, 0, 75) normal (0, 0, 1) x axis (-1, 0, 0)
  line L1 (-11.9644, -60.9879) -> (-19.9644, -60.9879)
  line L2 (-11.9644, -52.9879) -> (-11.9644, -60.9879)
  line L3 (-19.9644, -52.9879) -> (-11.9644, -52.9879)
  line L4 (-19.9644, -60.9879) -> (-19.9644, -52.9879)
  line L5 (-19.9644, -57.9879) -> (-29.9644, -57.9879)
  line L6 (-19.9644, -59.9879) -> (-19.9644, -57.9879)
  line L7 (-29.9644, -59.9879) -> (-19.9644, -59.9879)
  line L8 (-29.9644, -57.9879) -> (-29.9644, -59.9879)
  line L9 (-14.9644, -42.9879) -> (-14.9644, -52.9879)
  line L10 (-12.9644, -42.9879) -> (-14.9644, -42.9879)
  line L11 (-14.9644, -52.9879) -> (-12.9644, -52.9879)
  line L12 (-12.9644, -52.9879) -> (-12.9644, -42.9879)
  line L13 (-18.9144, -59.9379) -> (-13.0144, -59.9379)
  line L14 (-18.9144, -54.0379) -> (-18.9144, -59.9379)
  line L15 (-13.0144, -54.0379) -> (-18.9144, -54.0379)
  line L16 (-13.0144, -59.9379) -> (-13.0144, -54.0379)
  line L17 (-18.9644, -59.9879) -> (-12.9644, -59.9879)
  line L18 (-18.9644, -53.9879) -> (-18.9644, -59.9879)
  line L19 (-12.9644, -53.9879) -> (-18.9644, -53.9879)
  line L20 (-12.9644, -59.9879) -> (-12.9644, -53.9879)
  circle C1 centre (-15.9644, -56.9879) radius 1.7
  dimension "M3_d_1_1" diameter C1 = 3.4
extrude "Extrude6" add sketch "left side holes" profile of L3 L4 L5 L6 L7 L8 L9 L10 L11 L12 against normal blind 10 named "d90_1_1" (magnitude of "-column_support_height_1_1")
chamfer "Chamfer3" distance 10 (= "column_support_height_1_1") named "d92_1_1"
hole "Hole1" HoleDepth 10 (= "column_support_height_1_1") named "d93_1_1" HoleDiameter 3.4 named "d94_1_1" TipAngle 118 named "d95_1_1"
sketch "Sketch4" plane through (0, 60.9879, 0) normal (0, 1, 0) x axis (-1, 0, 0)
  line L1 (-11.9644, 5) -> (-19.9644, 5)
  line L2 (-11.9644, 75) -> (-11.9644, 5)
  line L3 (-19.9644, 75) -> (-11.9644, 75)
  line L4 (-19.9644, 5) -> (-19.9644, 75)
  line L5 (-23.511, 60) -> (-11.9644, 60)
  line L6 (-25, 20) -> (-11.9644, 20)
  circle C1 centre (-15.9644, 60) radius 1.7
  circle C2 centre (-15.9644, 20) radius 1.7
  point P7 (-11.9644, 60)
  point P8 (-11.9644, 60)
  point P6 (-11.9644, 20)
  point P10 (-11.9644, 20)
  point P12 (-15.9644, 60)
  point P13 (-15.9644, 20)
  coincident P7 P8
  perpendicular L4 L5
  coincident P6 P10
  perpendicular L2 L6
  coincident L5 P12
  coincident L6 P13
  dimension "d103_1_1" diameter C1 = 3.4 (= "M3_d_1_1")
  dimension "d104_1_1" diameter C2 = 3.4 (= "M3_d_1_1")
  dimension "d105_1_1" distance L2 P12 = 4 (= "support_column_side / 2")
  dimension "d106_1_1" distance L2 P13 = 4 (= "support_column_side / 2")
extrude "Extrude7" add sketch "left side holes" profile of C1 L13 L14 L15 L16 along normal blind 1.45 (= "( top_cover_thickness / 2 ) - wall_clearance") named "d236_1_1"
position "Position7"
sketch "Sketch5" plane through (11.9644, 0, 0) normal (-1, 0, 0) x axis (0, -1, 0)
  line L1 (-52.9879, 5) -> (-60.9879, 5)
  line L2 (-52.9879, 75) -> (-52.9879, 5)
  line L3 (-60.9879, 75) -> (-52.9879, 75)
  line L4 (-60.9879, 5) -> (-60.9879, 75)
  line L5 (-56.5129, 75) -> (-60.9879, 75)
  line L6 (-56.5129, 65) -> (-56.5129, 75)
  line L7 (-60.9879, 65) -> (-56.5129, 65)
  line L8 (-60.9879, 75) -> (-60.9879, 65)
  line L9 (-56.4129, 5) -> (-60.9879, 5)
  line L10 (-56.4129, 15) -> (-56.4129, 5)
  line L11 (-60.9879, 15) -> (-56.4129, 15)
  line L12 (-60.9879, 5) -> (-60.9879, 15)
  point P5 (-60.9879, 75)
  point P6 (-60.9879, 75)
  point P2 (-60.9879, 5)
  point P10 (-60.9879, 5)
  point P7 (-56.5129, 75)
  point P11 (-56.4129, 5)
  point P13 (-60.9879, 15)
  horizontal L5
  vertical L6
  horizontal L7
  vertical L8
  coincident P5 P6
  horizontal L9
  vertical L10
  horizontal L11
  vertical L12
  coincident P2 P10
  dimension "d271_1" distance P6 P7 = 4.475 (= "side_wall_col_length / 2 - wall_clearance")
  dimension "d272_1" distance L5 L7 = 10 (= "column_support_height")
  dimension "d273_1" distance P10 P11 = 4.575 (= "side_wall_col_length / 2 + wall_clearance")
  dimension "d274_1" distance P10 P13 = 10 (= "column_support_height")
extrude "Extrude8" add sketch "Sketch5" profile of L1 L3 L4 L5 L6 L7 L8 L9 L10 L11 L12 along normal blind 2 (= "2 * ( plate_square_thick - side_wall_col_length + wall_clearance )") named "d275_1"
mirror "Mirror1" mirrorStitchTolerance 0.1 named "d278_1"
position "Position8"
work_plane "WorkPlane1" AlongDistance 1 (= "( plate_square_thick - support_column_side ) / 2")
sketch "Sketch6" plane through (0, 60.9879, 0) normal (0, 1, 0) x axis (-1, 0, 0)
  line L1 (-11.9644, 15) -> (-9.9644, 15)
  line L2 (-11.9644, 65) -> (-11.9644, 15)
  line L3 (-9.9644, 65) -> (-11.9644, 65)
  line L4 (-9.9644, 15) -> (-9.9644, 65)
  line L5 (-1.9644, 5) -> (-19.9644, 5)
  line L6 (-1.9644, 75) -> (-1.9644, 5)
  line L7 (-19.9644, 75) -> (-1.9644, 75)
  line L8 (-19.9644, 5) -> (-19.9644, 75)
  line L9 (-5.9644, 5) -> (-15.9644, 5)
  line L10 (-5.9644, 15) -> (-5.9644, 5)
  line L11 (-15.9644, 15) -> (-5.9644, 15)
  line L12 (-15.9644, 5) -> (-15.9644, 15)
  line L13 (-5.9644, 75) -> (-15.9644, 75)
  line L14 (-5.9644, 65) -> (-5.9644, 75)
  line L15 (-15.9644, 65) -> (-5.9644, 65)
  line L16 (-15.9644, 75) -> (-15.9644, 65)
  point P10 (-15.9644, 5)
  point P14 (-15.9644, 75)
  point P15 (-5.9644, 75)
  point P17 (-15.9644, 65)
  horizontal L9
  vertical L10
  horizontal L11
  vertical L12
  coincident L5 P10
  horizontal L13
  vertical L14
  horizontal L15
  vertical L16
  coincident L7 P14
  dimension "d299" distance L10 L12 = 10 (= "column_support_height")
  dimension "d300" distance L9 L11 = 10 (= "column_support_height")
  dimension "d301" distance L8 L12 = 4 (= "support_column_side / 2")
  dimension "d302" distance P14 P15 = 10 (= "column_support_height")
  dimension "d303" distance P14 P17 = 10 (= "column_support_height")
  dimension "d304" distance L8 L16 = 4 (= "support_column_side / 2")
mirror "Mirror2" mirrorStitchTolerance 0.1
extrude "Extrude9" add sketch "Sketch6" profile of L1 L3 L5 L7 L9 L10 L11 L12 L13 L14 L15 L16 along normal blind 2 (= "plate_square_thick - support_column_side")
